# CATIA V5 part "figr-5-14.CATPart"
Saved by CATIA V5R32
Part number: Part1
Bounding box of the stored display mesh (mm): x 0 to 150, y -70 to 70, z -150 to 69.804
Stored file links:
  D:\PROJECTS\Project 2022\CATIA V5 6R 2022\Resources\Part Files\c05_catia_v5_6r2022_prt\figr-5-14.CATPart
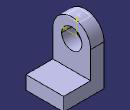
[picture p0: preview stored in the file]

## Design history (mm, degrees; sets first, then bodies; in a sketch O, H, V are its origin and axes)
Set1
  Plane1: type Offset, RefPlane face of Pad1, Offset -18, reversed
  Plane2: type Tangent, Support face of Pad1, RefPoint Sketch3
Body1 (main body)
  Sketch1 on yz-plane, origin (0, 0, 0), H (0, 1, 0), V (0, 0, 1)
    arc A1 centre (0, 0) radius 70 from (70, 0) to (-70, 0) ccw
    point P1 (70, 0)
    point P2 (-70, 0)
    line L1 (-70, 0) -> (-70, -150)
    line L2 (-70, -150) -> (70, -150)
    line L3 (70, -150) -> (70, 0)
    circle A2 centre (0, 0) radius 37.5
    radius A1 = 70
    radius A2 = 37.5
    distance O L2 = 150
    coincidence: P1 H, P2 H
    tangency: L1 A1, L3 A1
    horizontal: L2 H
  Pad1: profile Sketch1, direction (1, 0, 0), length 50
  Sketch2 on face of Pad1, origin (50, 0, 0), H (0, 1, 0), V (0, 0, 1)
    line L1 (-70, -150) -> (70, -150)
    line L2 (70, -150) -> (70, -100)
    line L3 (70, -100) -> (-70, -100)
    line L4 (-70, -100) -> (-70, -150)
    reference projected line E1 (-70, -150) -> (70, -150) from edge [face of Pad1 | face of Pad1]
    reference projected line E2 (-70, 0) -> (-70, -150) from edge [face of Pad1 | face of Pad1]
    reference projected line E3 (70, -150) -> (70, 0) from edge [face of Pad1 | face of Pad1]
    length L2 = 50
    horizontal: L1 H, L3 H
    vertical: L2 V, L4 V
    coincidence: L1 E1, E2 L4, L2 E3
  Pad2: profile Sketch2, direction (1, 0, 0), length 100
  Sketch3 on Plane1, origin (32, 0, 0), H (0, -1, 0), V (0, 0, 1)
    point P1 (-7.2142, 69.6273)
    reference projected arc E1 centre (0, 0) radius 70 from (70, 0) to (-70, 0) ccw from edge [face of Pad1 | face of Pad1]
    coincidence: P1 E1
